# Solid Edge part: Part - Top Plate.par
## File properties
Author: hhakima
Template: Normal.par
Last saved by: Houman
Revision: 45
Application: Solid Edge
Material: Aluminum, 6061-T6
Face Style: Aluminum
Fill Style: ANSI38(Aluminum)
Virtual Style: Polished aluminum
Coef. of Thermal Exp: 2.3e-05
Thermal Conductivity: 180.0
Specific Heat: 920.0
Modulus of Elasticity: 68947570000.0
Poission's Ratio: 0.33
Yield Stress: 275790280.0
Ultimate Stress: 310264065.0
Elongation: 0.0
Density: 2712.000 kg/m^3
Accuracy: 0.990
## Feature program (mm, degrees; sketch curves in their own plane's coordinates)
sketch for "unnamed Protrusion 1" plane through (0, 0, 0) normal (0, 0, 1) x-axis (1, 0, 0)
  line (-26.548, 15.0752) -> (29.452, 15.0752)
  line (29.452, 15.0752) -> (29.452, 123.0752)
  line (29.452, 123.0752) -> (-26.548, 123.0752)
  line (-26.548, 123.0752) -> (-26.548, 15.0752)
extrude "unnamed Protrusion 1" add finite 2 along -normal
sketch for "unnamed Hole 1" plane through (-8.798, 41.0752, 0) normal (0, 0, 1) x-axis (1, 0, 0)
hole "unnamed Hole 1" through
sketch for "unnamed Hole 2" plane through (-8.798, 41.0752, 0) normal (0, 0, 1) x-axis (1, 0, 0)
hole "unnamed Hole 2" through
sketch for "unnamed Hole 3" plane through (-8.798, 41.0752, 0) normal (0, 0, 1) x-axis (1, 0, 0)
hole "unnamed Hole 3" through
sketch for "unnamed Hole 4" plane through (-8.798, 41.0752, 0) normal (0, 0, 1) x-axis (1, 0, 0)
hole "unnamed Hole 4" through
sketch for "unnamed Hole 5" plane through (-8.798, 41.0752, 0) normal (0, 0, 1) x-axis (1, 0, 0)
hole "unnamed Hole 5" through
sketch for "unnamed Hole 6" plane through (-8.798, 41.0752, 0) normal (0, 0, 1) x-axis (1, 0, 0)
  hole centre (11.75, 65) bore radius 1.1
hole "unnamed Hole 6" through
sketch for "unnamed Hole 7" plane through (-8.798, 41.0752, 0) normal (0, 0, 1) x-axis (1, 0, 0)
  hole centre (11.75, 38) bore radius 1.1
hole "unnamed Hole 7" through
sketch for "unnamed Hole 8" plane through (-8.798, 41.0752, 0) normal (0, 0, 1) x-axis (1, 0, 0)
  hole centre (4.25, 57.5) bore radius 1.1
hole "unnamed Hole 8" through
sketch for "ExtrudedProtrusion_2" #1 plane through (-6.548, 41.0752, 0) normal (0, 0, 1) x-axis (1, 0, 0)
sketch for "ExtrudedProtrusion_2" #2 plane through (-6.548, 41.0752, 0) normal (0, 0, 1) x-axis (1, 0, 0)
  line (36, 42.5) -> (41, 42.5)
  line (41, 42.5) -> (41, 48)
  line (41, 48) -> (36, 48)
  line (36, 48) -> (36, 42.5)
sketch for "ExtrudedProtrusion_2" #3 plane through (-6.548, 41.0752, 0) normal (0, 0, 1) x-axis (1, 0, 0)
  line (36, -26) -> (41, -26)
  line (41, -26) -> (41, -21)
  line (41, -21) -> (36, -21)
  line (36, -21) -> (36, -26)
sketch for "ExtrudedProtrusion_2" #4 plane through (-6.548, 41.0752, 0) normal (0, 0, 1) x-axis (1, 0, 0)
extrude "ExtrudedProtrusion_2" add finite 2 along -normal
sketch for "Hole_7" plane through (-4.048, 41.0752, 0) normal (0, 0, 1) x-axis (1, 0, 0)
  hole centre (36, 79.5) bore radius 1.1
  dimension (linear) = 36
  dimension (linear) = 36
  dimension (linear) = 36
  dimension (linear) = 36
hole "Hole_7" diameter 2.2 through
sketch for "unnamed Hole 9" plane through (-4.048, 41.0752, 0) normal (0, 0, 1) x-axis (1, 0, 0)
  hole centre (36, 45.25) bore radius 1.1
hole "unnamed Hole 9" through
sketch for "unnamed Hole 10" plane through (-4.048, 41.0752, 0) normal (0, 0, 1) x-axis (1, 0, 0)
  hole centre (36, 10.75) bore radius 1.1
hole "unnamed Hole 10" through
sketch for "unnamed Hole 11" plane through (-4.048, 41.0752, 0) normal (0, 0, 1) x-axis (1, 0, 0)
  hole centre (36, -23.5) bore radius 1.1
hole "unnamed Hole 11" through
pattern "unnamed Pattern 1" of "Hole_7", "unnamed Hole 9", "unnamed Hole 10", "unnamed Hole 11"
mirror "unnamed Mirror 1" of "ExtrudedProtrusion_2", "unnamed Pattern 1" about plane through (1.452, 41.0752, -1) normal (-1, 0, 0)
extrude "unnamed Protrusion 2" add finite 2
hole "unnamed Hole 12" through
hole "unnamed Hole 13" through
hole "unnamed Hole 14" through
hole "unnamed Hole 15" through
sketch for "unnamed Protrusion 3" #1 plane through (-5.048, 15.0752, -1) normal (0, -1, 0) x-axis (1, 0, 0)
  line (24.5, 1) -> (29.5, 1)
  line (29.5, 1) -> (29.5, 6)
  line (29.5, 6) -> (24.5, 6)
  line (24.5, 6) -> (24.5, 1)
sketch for "unnamed Protrusion 3" #2 plane through (-5.048, 15.0752, -1) normal (0, -1, 0) x-axis (1, 0, 0)
  line (-16.5, 1) -> (-11.5, 1)
  line (-11.5, 1) -> (-11.5, 6)
  line (-11.5, 6) -> (-16.5, 6)
  line (-16.5, 6) -> (-16.5, 1)
  dimension (linear) = 16.5
  dimension (linear) = 11.5
extrude "unnamed Protrusion 3" add finite 3 along -normal
mirror "unnamed Mirror 2" of "unnamed Protrusion 3" about plane through (-5.048, 69.0752, -1) normal (0, 1, 0)
extrude "unnamed Protrusion 4" add finite 3
sketch for "unnamed Hole 16" plane through (11.952, 18.0752, 2.5) normal (0, 1, 0) x-axis (-1, 0, 0)
  hole centre (31, 0) bore radius 0.7835
hole "unnamed Hole 16" through
sketch for "unnamed Hole 17" plane through (11.952, 18.0752, 2.5) normal (0, 1, 0) x-axis (-1, 0, 0)
  hole centre (-10, 0) bore radius 0.7835
  dimension (linear) = 10
hole "unnamed Hole 17" through
pattern "unnamed Pattern 2" of "unnamed Hole 16", "unnamed Hole 17"
mirror "unnamed Mirror 3" of "unnamed Pattern 2" about plane through (-5.048, 69.0752, -1) normal (0, 1, 0)
hole "unnamed Hole 18" through
hole "unnamed Hole 19" through
pattern "unnamed Pattern 3" of "unnamed Hole 1", "unnamed Hole 2", "unnamed Hole 3", "unnamed Hole 4", "unnamed Hole 5", "unnamed Hole 6", "unnamed Hole 7", "unnamed Hole 8"
Other named dimensions: "Hole_1": Diameter = 2.2 mm
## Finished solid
Body 1: solid body, 66 faces, 172 edges, 88 vertices.
  Faces by surface: plane 46, cylinder 20
  Edges by curve: line 132, circle 40
Bounding box of the edges (mm): 66.000 x 108.000 x 7.000, from (-31.548, 15.0752, -2) to (34.452, 123.0752, 5).
Cylindrical faces by radius (mm): R0.7835 x4, R1.1 x16
Planar faces by outward normal: +x 11, +y 9, +z 5, -x 11, -y 9, -z 1
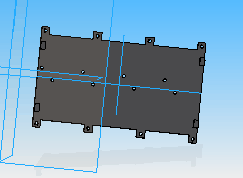
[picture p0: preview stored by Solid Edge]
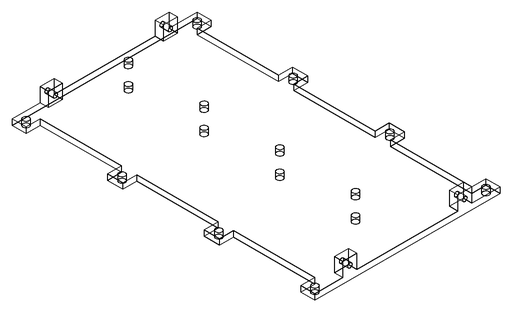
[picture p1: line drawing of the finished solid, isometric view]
